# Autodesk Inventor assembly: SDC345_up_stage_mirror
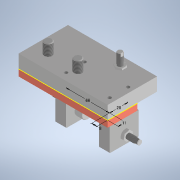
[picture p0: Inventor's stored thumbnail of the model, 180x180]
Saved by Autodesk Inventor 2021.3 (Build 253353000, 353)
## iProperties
Created: 2022-02
Part Number: SDC345_up_stage_mirror
Document SubType Name: Assembly
Designer: kengo
Author: kengo
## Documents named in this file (7)
- C:\Users\kengo\Documents\S2S_frame\SDC345\frame_misumi_ver12\upper-stage\SDC345_up_stage_mirror.iam
- C:\Users\kengo\Documents\S2S_frame\SDC345\frame_misumi_ver12\upper-stage\SDC_upper_stage_AlPlate_mirror.ipt
- C:\Users\kengo\Documents\S2S_frame\SDC345\frame_misumi_ver12\upper-stage\CBM12-25.ipt
- C:\Users\kengo\Documents\S2S_frame\SDC345\frame_misumi_ver12\upper-stage\SDC_upper_stage_CFPlate.ipt
- C:\Users\kengo\Documents\S2S_frame\SDC345\frame_misumi_ver12\upper-stage\AJSN8-20.ipt
- C:\Users\kengo\Documents\S2S_frame\SDC345\frame_misumi_ver12\upper-stage\SCB6-55.ipt
- C:\Users\kengo\Documents\S2S_frame\SDC345\frame_misumi_ver12\upper-stage\UNST8-40.iam
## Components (13 placed, 6 different names)
1. SDC_upper_stage_AlPlate_mirror:1 — 回転:1, 回転:2, メイト:1, フラッシュ:1, フラッシュ:2, 回転:6
2. CBM12-25:1 — 回転:1
3. CBM12-25:2 — 回転:2
4. SDC_upper_stage_CFPlate:1 — メイト:1, フラッシュ:1, フラッシュ:2, メイト:2, フラッシュ:3, 挿入:1, メイト:3, 挿入:2, 挿入:3
5. AJSN8-20:1 — メイト:2, フラッシュ:3, 挿入:1, リジッド:1, 回転:3, 回転:7
6. AJSN8-20:2 — メイト:3, 挿入:2, 挿入:3, 回転:4, 回転:5, リジッド:2
7. SCB6-55:1 — リジッド:1
8. SCB6-55:2 — 回転:3
9. SCB6-55:3 — 回転:4
10. SCB6-55:4 — 回転:5
11. UNST8-40:1 [sub-assembly] — 回転:7
12. UNST8-40:2 [sub-assembly] — リジッド:2
13. UNST8-40:3 [sub-assembly] — 回転:6
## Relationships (18: RevoluteJoint 7, Mate 3, Flush 3, Insert 3, WeldJoint 2)
- 回転:1 [RevoluteJoint]: SDC_upper_stage_AlPlate_mirror:1 ↔ CBM12-25:1
- 回転:2 [RevoluteJoint]: SDC_upper_stage_AlPlate_mirror:1 ↔ CBM12-25:2
- メイト:1 [Mate]: SDC_upper_stage_AlPlate_mirror:1 ↔ SDC_upper_stage_CFPlate:1
- フラッシュ:1 [Flush]: SDC_upper_stage_AlPlate_mirror:1 ↔ SDC_upper_stage_CFPlate:1
- フラッシュ:2 [Flush]: SDC_upper_stage_AlPlate_mirror:1 ↔ SDC_upper_stage_CFPlate:1
- メイト:2 [Mate]: SDC_upper_stage_CFPlate:1 ↔ AJSN8-20:1
- フラッシュ:3 [Flush]: SDC_upper_stage_CFPlate:1 ↔ AJSN8-20:1
- 挿入:1 [Insert]: SDC_upper_stage_CFPlate:1 ↔ AJSN8-20:1
- メイト:3 [Mate]: SDC_upper_stage_CFPlate:1 ↔ AJSN8-20:2
- 挿入:2 [Insert]: SDC_upper_stage_CFPlate:1 ↔ AJSN8-20:2
- 挿入:3 [Insert]: SDC_upper_stage_CFPlate:1 ↔ AJSN8-20:2
- リジッド:1 [WeldJoint]: AJSN8-20:1 ↔ SCB6-55:1
- 回転:3 [RevoluteJoint]: AJSN8-20:1 ↔ SCB6-55:2
- 回転:4 [RevoluteJoint]: AJSN8-20:2 ↔ SCB6-55:3
- 回転:5 [RevoluteJoint]: AJSN8-20:2 ↔ SCB6-55:4
- 回転:6 [RevoluteJoint]: SDC_upper_stage_AlPlate_mirror:1 ↔ UNST8-40:3
- 回転:7 [RevoluteJoint]: AJSN8-20:1 ↔ UNST8-40:1
- リジッド:2 [WeldJoint]: AJSN8-20:2 ↔ UNST8-40:2
